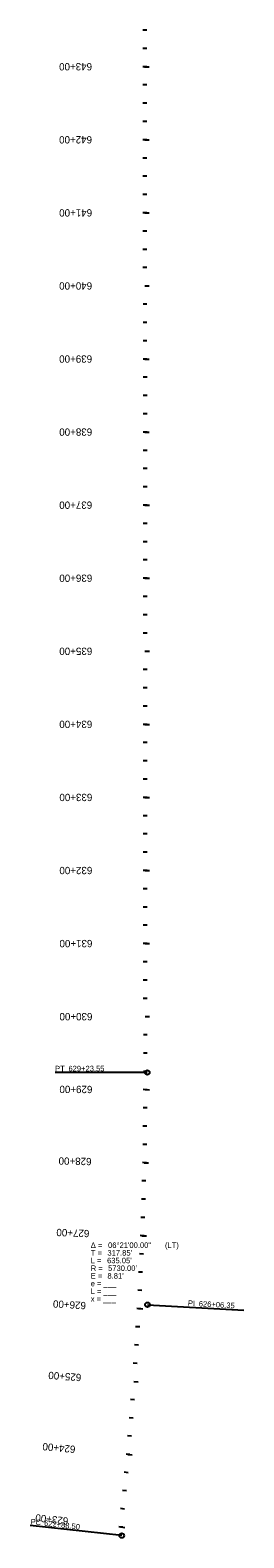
# Model space of a CAD drawing. Extents: x 16453950 to 16454580, y 7022804 to 7039381.
# Drawn here: x 16454282 to 16454574, y 7029026 to 7031090 of the extents above; entities that cross this region are included whole.
import ezdxf

# ---------------------------------------------------------------- set-up
doc = ezdxf.new("R2010")
doc.units = 0
for name, color, linetype in [('TextAlignment', 7, 'Continuous'), ('TextAlignmentLrg', 7, 'Continuous'), ('TextAlignmentSml', 7, 'Continuous')]:
    doc.layers.add(name, color=color, linetype=linetype)

msp = doc.modelspace()

# ---------------------------------------------------------------- linework, layer by layer
at = {"layer": 'TextAlignment'}
for p, q in [((16454441.9, 7029663.2), (16454315.9, 7029663.1)), ((16454315.9, 7029663.1), (16454315.9, 7029663.1)), ((16454442.1, 7029345.3), (16454573.9, 7029338.1)), ((16454573.9, 7029338.1), (16454573.9, 7029338.1)), ((16454407, 7029029.4), (16454281.8, 7029043.3)), ((16454281.8, 7029043.3), (16454281.8, 7029043.3))]:
    msp.add_line(p, q, dxfattribs=at)
for centre in [(16454441.9, 7029663.2), (16454442.1, 7029345.3), (16454407, 7029029.4)]:
    msp.add_circle(centre, 3.12, dxfattribs=at)
at = {"layer": 'TextAlignmentLrg'}
for p, q in [((16454441.4, 7031039.6), (16454435.9, 7031039.6)), ((16454441.4, 7030939.6), (16454436, 7030939.6)), ((16454441.5, 7030839.6), (16454436, 7030839.6)), ((16454438.4, 7030739.6), (16454444.6, 7030739.6)), ((16454441.5, 7030639.6), (16454436.1, 7030639.6)), ((16454441.6, 7030539.6), (16454436.1, 7030539.6)), ((16454441.6, 7030439.6), (16454436.2, 7030439.6)), ((16454441.7, 7030339.6), (16454436.2, 7030339.6)), ((16454438.6, 7030239.6), (16454444.8, 7030239.6)), ((16454441.7, 7030139.6), (16454436.3, 7030139.6)), ((16454441.8, 7030039.6), (16454436.3, 7030039.6)), ((16454441.8, 7029939.6), (16454436.4, 7029939.6)), ((16454441.9, 7029839.6), (16454436.4, 7029839.6)), ((16454438.8, 7029739.6), (16454445, 7029739.6)), ((16454441.9, 7029639.6), (16454436.4, 7029639.7)), ((16454440.7, 7029539.7), (16454435.2, 7029539.8)), ((16454437.7, 7029439.7), (16454432.2, 7029439.9)), ((16454432.9, 7029339.8), (16454427.5, 7029340.1)), ((16454423.4, 7029240.2), (16454429.5, 7029239.8)), ((16454418.2, 7029140.4), (16454412.8, 7029140.9)), ((16454408.3, 7029040.9), (16454402.9, 7029041.5))]:
    msp.add_line(p, q, dxfattribs=at)
at = {"layer": 'TextAlignmentSml'}
for p, q in [((16454441.4, 7031089.6), (16454435.9, 7031089.6)), ((16454441.4, 7031064.6), (16454435.9, 7031064.6)), ((16454438.3, 7031039.6), (16454444.4, 7031039.6)), ((16454441.4, 7031014.6), (16454435.9, 7031014.6)), ((16454441.4, 7030989.6), (16454435.9, 7030989.6)), ((16454441.4, 7030964.6), (16454436, 7030964.6)), ((16454438.4, 7030939.6), (16454444.5, 7030939.6)), ((16454441.4, 7030914.6), (16454436, 7030914.6)), ((16454441.4, 7030889.6), (16454436, 7030889.6)), ((16454441.5, 7030864.6), (16454436, 7030864.6)), ((16454438.4, 7030839.6), (16454444.5, 7030839.6)), ((16454441.5, 7030814.6), (16454436, 7030814.6)), ((16454441.5, 7030789.6), (16454436, 7030789.6)), ((16454441.5, 7030764.6), (16454436, 7030764.6)), ((16454438.4, 7030739.6), (16454444.6, 7030739.6)), ((16454441.5, 7030714.6), (16454436.1, 7030714.6)), ((16454441.5, 7030689.6), (16454436.1, 7030689.6)), ((16454441.5, 7030664.6), (16454436.1, 7030664.6)), ((16454438.5, 7030639.6), (16454444.6, 7030639.6)), ((16454441.6, 7030614.6), (16454436.1, 7030614.6)), ((16454441.6, 7030589.6), (16454436.1, 7030589.6)), ((16454441.6, 7030564.6), (16454436.1, 7030564.6)), ((16454438.5, 7030539.6), (16454444.6, 7030539.6)), ((16454441.6, 7030514.6), (16454436.1, 7030514.6)), ((16454441.6, 7030489.6), (16454436.1, 7030489.6)), ((16454441.6, 7030464.6), (16454436.2, 7030464.6)), ((16454438.6, 7030439.6), (16454444.7, 7030439.6)), ((16454441.6, 7030414.6), (16454436.2, 7030414.6)), ((16454441.6, 7030389.6), (16454436.2, 7030389.6)), ((16454441.7, 7030364.6), (16454436.2, 7030364.6)), ((16454438.6, 7030339.6), (16454444.7, 7030339.6)), ((16454441.7, 7030314.6), (16454436.2, 7030314.6)), ((16454441.7, 7030289.6), (16454436.2, 7030289.6)), ((16454441.7, 7030264.6), (16454436.2, 7030264.6)), ((16454438.6, 7030239.6), (16454444.8, 7030239.6)), ((16454441.7, 7030214.6), (16454436.3, 7030214.6)), ((16454441.7, 7030189.6), (16454436.3, 7030189.6)), ((16454441.7, 7030164.6), (16454436.3, 7030164.6)), ((16454438.7, 7030139.6), (16454444.8, 7030139.6)), ((16454441.8, 7030114.6), (16454436.3, 7030114.6)), ((16454441.8, 7030089.6), (16454436.3, 7030089.6)), ((16454441.8, 7030064.6), (16454436.3, 7030064.6)), ((16454438.7, 7030039.6), (16454444.8, 7030039.6)), ((16454441.8, 7030014.6), (16454436.3, 7030014.6)), ((16454441.8, 7029989.6), (16454436.3, 7029989.6)), ((16454441.8, 7029964.6), (16454436.4, 7029964.6)), ((16454438.8, 7029939.6), (16454444.9, 7029939.6)), ((16454441.8, 7029914.6), (16454436.4, 7029914.6)), ((16454441.8, 7029889.6), (16454436.4, 7029889.6)), ((16454441.9, 7029864.6), (16454436.4, 7029864.6)), ((16454438.8, 7029839.6), (16454444.9, 7029839.6)), ((16454441.9, 7029814.6), (16454436.4, 7029814.6)), ((16454441.9, 7029789.6), (16454436.4, 7029789.6)), ((16454441.9, 7029764.6), (16454436.4, 7029764.6)), ((16454438.8, 7029739.6), (16454445, 7029739.6)), ((16454441.9, 7029714.6), (16454436.5, 7029714.6)), ((16454441.9, 7029689.6), (16454436.5, 7029689.6)), ((16454441.9, 7029664.6), (16454436.5, 7029664.6)), ((16454438.8, 7029639.7), (16454445, 7029639.6)), ((16454441.7, 7029614.6), (16454436.3, 7029614.7)), ((16454441.5, 7029589.6), (16454436, 7029589.7)), ((16454441.1, 7029564.6), (16454435.7, 7029564.7)), ((16454437.6, 7029539.7), (16454443.7, 7029539.6)), ((16454440.1, 7029514.7), (16454434.6, 7029514.8)), ((16454439.4, 7029489.7), (16454433.9, 7029489.8)), ((16454438.6, 7029464.7), (16454433.1, 7029464.9)), ((16454434.6, 7029439.8), (16454440.7, 7029439.6)), ((16454436.6, 7029414.7), (16454431.2, 7029415)), ((16454435.5, 7029389.7), (16454430.1, 7029390)), ((16454434.3, 7029364.8), (16454428.8, 7029365.1)), ((16454429.9, 7029340), (16454436, 7029339.6)), ((16454431.5, 7029314.9), (16454426, 7029315.2)), ((16454429.9, 7029289.9), (16454424.5, 7029290.3)), ((16454428.2, 7029265), (16454422.8, 7029265.3)), ((16454423.4, 7029240.2), (16454429.5, 7029239.8)), ((16454424.6, 7029215.1), (16454419.1, 7029215.5)), ((16454422.6, 7029190.2), (16454417.1, 7029190.6)), ((16454420.5, 7029165.3), (16454415, 7029165.7)), ((16454415.2, 7029140.6), (16454421.3, 7029140.1)), ((16454415.9, 7029115.5), (16454410.5, 7029116)), ((16454413.5, 7029090.6), (16454408.1, 7029091.1)), ((16454410.9, 7029065.7), (16454405.5, 7029066.3)), ((16454405.2, 7029041.2), (16454411.3, 7029040.5))]:
    msp.add_line(p, q, dxfattribs=at)

# ---------------------------------------------------------------- texts
at = {"layer": 'TextAlignment'}
for s, rotation, p in [('PT', 0.0231, (16454315.9, 7029664.8)), ('629+23.55', 0.0231, (16454334.1, 7029664.8)), ('PI ', 356.8481, (16454497.2, 7029344)), ('626+06.35', 356.8481, (16454512.1, 7029343.1)), ('PC', 353.6731, (16454282, 7029045)), ('622+88.50', 353.6731, (16454300.5, 7029042.9))]:
    msp.add_text(s, height=7.5, rotation=rotation, dxfattribs=at).set_placement(p)
for s, p in [('Δ = ', (16454364.6, 7029423.1)), ('06°21\'00.00"', (16454388.3, 7029423.1)), (' (LT)', (16454463.2, 7029423.1)), ('T = ', (16454364.6, 7029412.6)), ('L = ', (16454364.6, 7029402.1)), ("635.05'", (16454386.9, 7029402.1)), ("317.85'", (16454387.4, 7029412.6)), ('R = ', (16454364.6, 7029391.6)), ('E = ', (16454364.6, 7029381.1)), ("8.81'", (16454387.4, 7029381.1)), ("5730.00'", (16454388.3, 7029391.6)), ('e = ___ ', (16454364.6, 7029370.6)), ('L = ___', (16454364.6, 7029360.1)), ('x = ___', (16454364.6, 7029349.6))]:
    msp.add_text(s, height=7.5, dxfattribs=at).set_placement(p)
at = {"layer": 'TextAlignmentLrg'}
for s, rotation, p in [('640+00', 180.0231, (16454366.5, 7030744.6)), ('635+00', 180.0231, (16454366.7, 7030244.6)), ('630+00', 180.0231, (16454366.9, 7029744.6)), ('625+00', 175.7879, (16454352, 7029250.5))]:
    msp.add_text(s, height=10.02, rotation=rotation, dxfattribs=at).set_placement(p)
at = {"layer": 'TextAlignmentSml'}
for s, rotation, p in [('643+00', 180.0231, (16454366.4, 7031044.6)), ('642+00', 180.0231, (16454366.4, 7030944.6)), ('641+00', 180.0231, (16454366.5, 7030844.6)), ('640+00', 180.0231, (16454366.5, 7030744.6)), ('639+00', 180.0231, (16454366.5, 7030644.6)), ('638+00', 180.0231, (16454366.6, 7030544.6)), ('637+00', 180.0231, (16454366.6, 7030444.6)), ('636+00', 180.0231, (16454366.7, 7030344.6)), ('635+00', 180.0231, (16454366.7, 7030244.6)), ('634+00', 180.0231, (16454366.7, 7030144.6)), ('633+00', 180.0231, (16454366.8, 7030044.6)), ('632+00', 180.0231, (16454366.8, 7029944.6)), ('631+00', 180.0231, (16454366.9, 7029844.6)), ('630+00', 180.0231, (16454366.9, 7029744.6)), ('629+00', 179.7876, (16454366.9, 7029644.9)), ('628+00', 178.7877, (16454365.8, 7029546.2)), ('627+00', 177.7877, (16454362.9, 7029447.6)), ('626+00', 176.7878, (16454358.3, 7029349)), ('625+00', 175.7879, (16454352, 7029250.5)), ('624+00', 174.788, (16454344, 7029152.2)), ('623+00', 173.788, (16454334.3, 7029054))]:
    msp.add_text(s, height=10.02, rotation=rotation, dxfattribs=at).set_placement(p)

doc.saveas('drawing.dxf')
